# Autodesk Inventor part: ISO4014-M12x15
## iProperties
Author: Tobben
Created: 2001-12
Part Number: ISO4014-M12x15
Document SubType Name: Modeling
Designer: Tobben
Control State: 0
Master: False
Checked Out: False
PropertySet Name: Design Tracking Control
Shininess: 64.0
Angle Display Precision: 2
Document Length Units: 11269
Document Angle Units: 11283
Document Time Units: 11279
Document Mass Units: 11290
Document Length Units Precision: 3
Document Angle Units Precision: 2
Compacted: False
PropertySet Name: _Private Model Information
Density: 0.0
Volumn: 0.0
Area: 0.0
PropertySet Name: Model Information
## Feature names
1. Base1
